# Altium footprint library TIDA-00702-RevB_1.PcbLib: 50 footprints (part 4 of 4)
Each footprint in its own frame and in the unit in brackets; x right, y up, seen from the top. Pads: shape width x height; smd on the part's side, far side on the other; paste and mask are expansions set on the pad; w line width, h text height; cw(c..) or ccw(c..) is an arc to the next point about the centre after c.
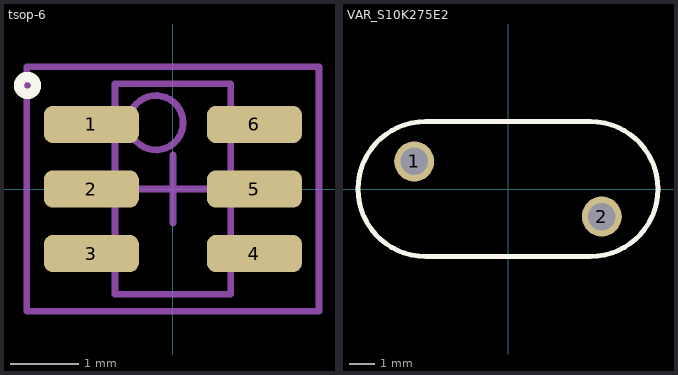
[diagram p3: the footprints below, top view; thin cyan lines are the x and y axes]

## tsop-6 [mm] "TSOP, 6-Leads, Body 3.1x1.7mm (max), Pitch 0.95mm, IPC Medium Density"
height 1.1
pads (6):
  rrect50% 1.4x0.55 smd: 1(-1.2,0.95) 2(-1.2,0) 3(-1.2,-0.95) 4(1.2,-0.95) 5(1.2,0) 6(1.2,0.95)
Top Overlay:
  circle w0.152: c-2.14,1.524 r0.125
Mechanical 5:
  text ".Designator" at -0.838,-0.533 h0.89
Mechanical 13:
  circle w0.1: c-0.25,0.975 r0.4
  lines w0.1: -0.85,-1.55 0.85,-1.55 0.85,1.55 -0.85,1.55 -0.85,-1.55
Mechanical 15:
  lines w0.1: -0.5,0 0.5,0 ; 0,-0.5 0,0.5 ; -2.15,-1.8 2.15,-1.8 2.15,1.8 -2.15,1.8 -2.15,-1.8
3D body: height 1.1, standoff 0.1, extent -0.85,-1.55 0.85,1.55
3D body: height 1.1, standoff 1.1, extent -0.657,0.568 0.157,1.382

## VAR_S10K275E2 [mm] "EPCOS"
height 14.5
pads (2):
  round 1.6 hole 1.1: 1(-3.75,1.1) 2(3.75,-1.1)
Top Overlay:
  lines w0.2: -3.3,-2.7 cw(c-3.3,0) -3.3,2.7 3.3,2.7 cw(c3.3,0) 3.3,-2.7 -3.3,-2.7
Mechanical 5:
  lines w0.1: -3.3,-2.7 cw(c-3.3,0) -3.3,2.7 3.3,2.7 cw(c3.3,0) 3.3,-2.7 -3.3,-2.7
  text ".Designator" at -0.203,1.067 h0.89
3D body: height 7, standoff -3, extent -4.172,0.676 -3.325,1.524
3D body: height 7, standoff -3, extent 3.328,-1.524 4.175,-0.676
3D body: height 14.99, standoff 3.01, extent -5.976,-2.7 5.976,2.7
